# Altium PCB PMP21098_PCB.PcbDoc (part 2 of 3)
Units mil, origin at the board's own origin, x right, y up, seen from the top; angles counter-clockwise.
Board outline 5551.18 x 2125.98 mil, 4 copper layers (Top Layer, Signal Layer 1, Signal Layer 2, Bottom Layer), stack 61.6 mil thick; 197 components, 100 nets, 482 pads, 134 vias.
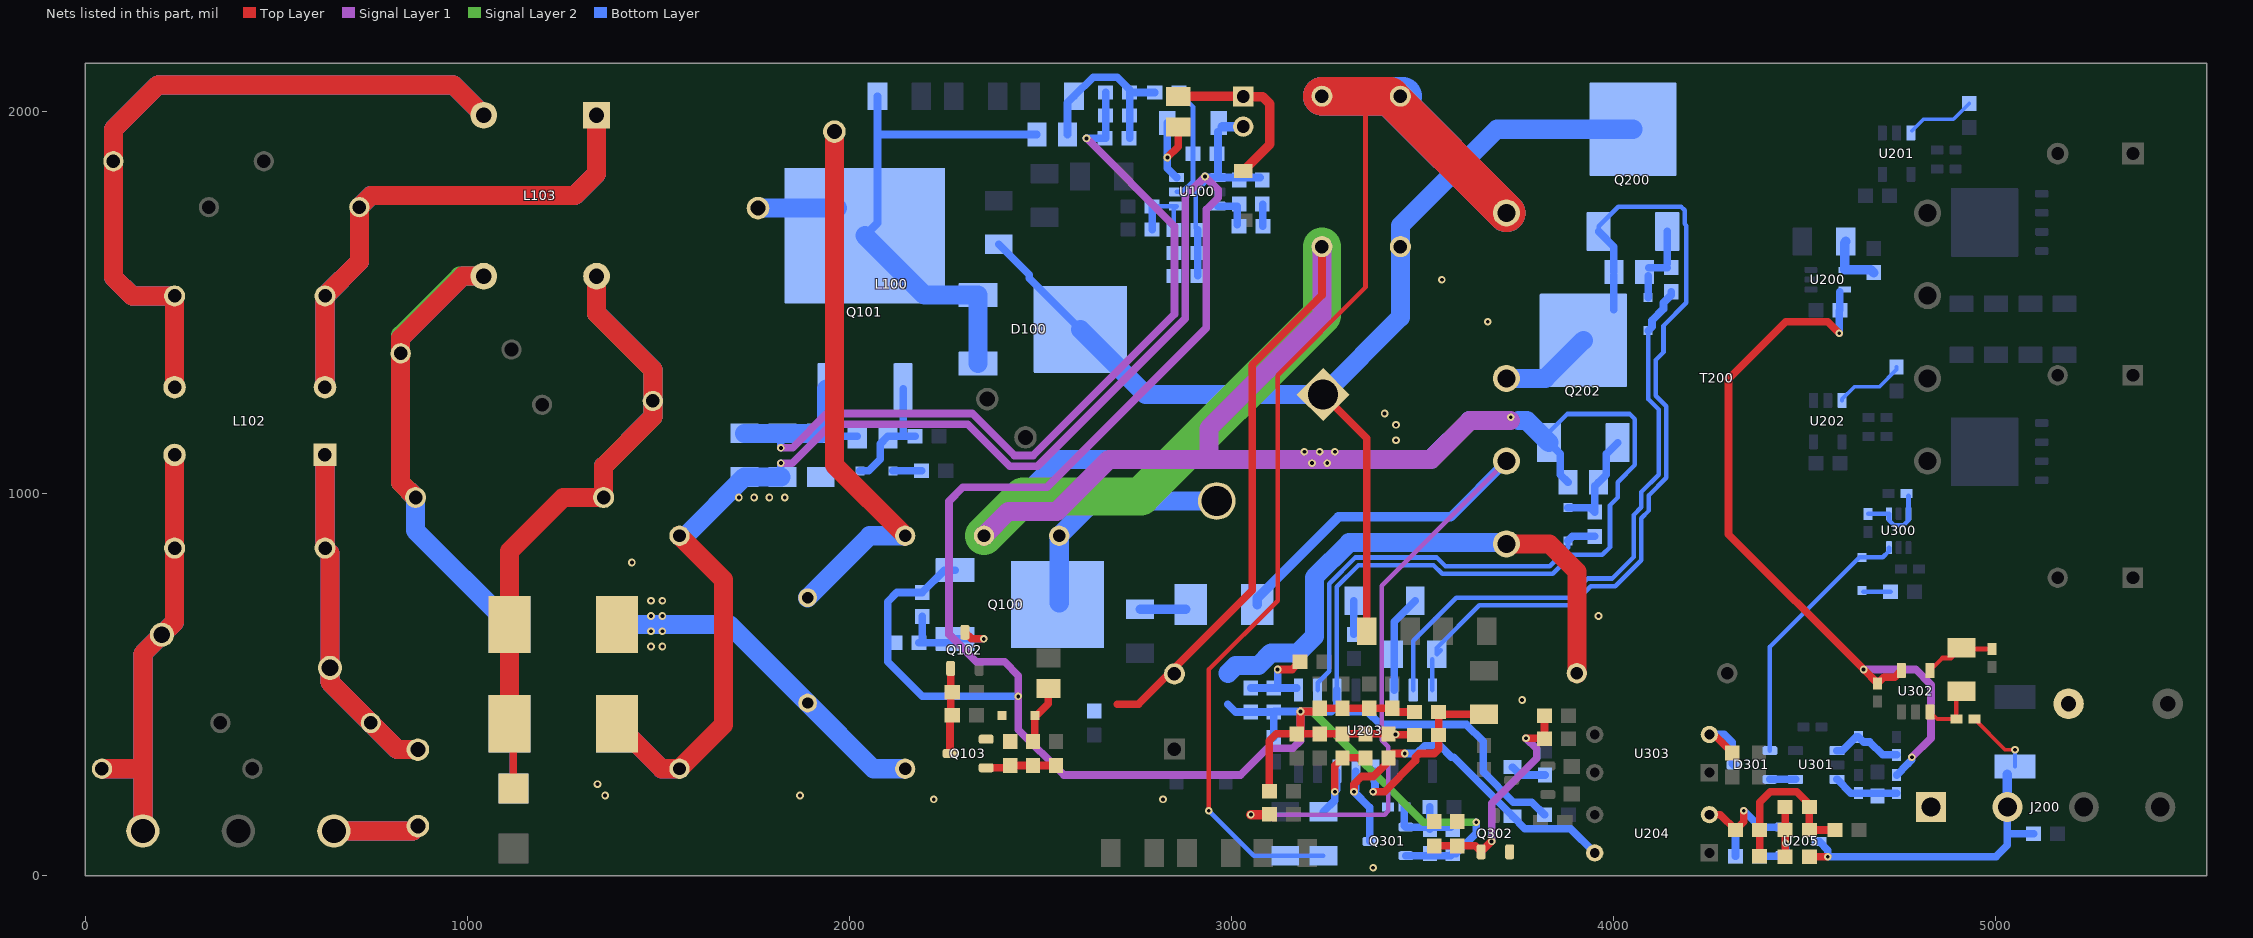
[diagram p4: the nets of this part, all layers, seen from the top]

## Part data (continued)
C122: "CAP, CERM, 10 pF, 10 V,+/- 10%, X7R, 0603", Cap_Case=0603, Manufacturer=AVX, Supplier Part Number 1=0603ZC100KAT2A-ND, TempCo=X7R, Tolerance_%=10, Value1=Unknown, Value2=10V, ValueDisplayed=10pF
C123: "CAP, CERM, 2200 pF, 50 V,+/- 10%, X7R, 0603", Cap_Case=0603, Manufacturer=Kemet, Supplier Part Number 1=399-1085-1-ND, TempCo=X7R, Tolerance_%=10, Value2=50V, ValueDisplayed=2200pF
C200 C213: "CAP, CERM, 1uF, 16V, +/-10%, X5R, 0603", Cap_Case=0603, Manufacturer=Kemet, Supplier Part Number 1=399-5090-1-ND, TempCo=X5R, Tolerance_%=10, Value1=Unknown, Value2=16V, ValueDisplayed=1µF
C201 C205: library part B32021A3332M289, "CAP FILM 10000PF 10% 630VDC RAD", Manufacturer="EPCOS (TDK)", Tolerance_%=20, Value1=Unknown, Value2=630V, ValueDisplayed=0.01µF
C202 C203 C211 C212: "CAP, CERM, 22 µF, 16 V,+/- 20%, X7R, 1206", Cap_Case=1206, Manufacturer="Taiyo Yuden", Supplier Part Number 1=587-4319-1-ND, TempCo=X7R, Tolerance_%=20, Value2=16V, ValueDisplayed=22µF
C204: "CAP, CERM, 1 µF, 25 V,+/- 10%, X5R, 1206", Cap_Case=1206, Manufacturer=MuRata, Supplier Part Number 1=490-1807-1-ND, TempCo=X5R, Tolerance_%=10, Value1="0.01 ohm", Value2=25V, ValueDisplayed=1µF
C206: "CAP, CERM, 150 pF, 630 V, +/- 5%, C0G/NP0, 1206", Cap_Case=1206, Manufacturer=MuRata, Supplier Part Number 1=490-5274-1-ND, TempCo=C0G/NP0, Tolerance_%=5, Value1=Unknown, Value2=630V, ValueDisplayed=150pF
C207: "CAP, CERM, 150 pF, 630 V,+/- 5%, C0G/NP0, 1206", Cap_Case=1206, Manufacturer=MuRata, Supplier Part Number 1=490-5274-1-ND, TempCo=C0G/NP0, Tolerance_%=5, Value2=630V, ValueDisplayed=150pF
C208: library part APS-160ELL331MJC5S, "CAP ALUM POLY 470UF 20% 16V T/H", Manufacturer=Chemi-Con, Tolerance_%=20, Value1="0.014 ohm", Value2=16V, ValueDisplayed=470µF
C209 C210: library part UHW1C222MHD, "CAP ALUM 2200UF 20% 16V RADIAL", Cap_Case=12.5x20mm, Manufacturer=Panasonic, Tolerance_%=20, Value2=16V, ValueDisplayed=2200µF
C215: library part CMP-0009602-2, "CAP, CERM, 2200 pF, 250 V, +/- 20%, E, Disc 10x8mm", Cap_Case=CAPRD1000W60D1000H1400, Manufacturer=MuRata, Supplier Part Number 1=490-7048-ND, TempCo=E, Tolerance_%=20%, Value1=Unknown, Value2=250V, ValueDisplayed=2200pF
C216 C218: "CAP, CERM, 2.2 µF, 16 V,+/- 20%, X5R, 0603", Cap_Case=0603, Manufacturer="Wurth Elektronik", Supplier Part Number 1=732-7915-1-ND, TempCo=X5R, Tolerance_%=20, Value2=16V, ValueDisplayed=2.2µF
C217 C219: "CAP, CERM, 0.1 µF, 25 V,+/- 5%, X7R, 0603", Cap_Case=0603, Manufacturer=AVX, Supplier Part Number 1=478-3713-1-ND, TempCo=X7R, Tolerance_%=5, Value1="0.05 ohm", Value2=25V, ValueDisplayed=0.1µF
C220: "CAP, CERM, 2.2 µF, 16 V, +/- 10%, X7R, 1206", Cap_Case=1206, Manufacturer=Kemet, Supplier Part Number 1=80-C1206C225K4R, TempCo=X7R, Tolerance_%=10, Value1="0.009 ohm", Value2=16V, ValueDisplayed=2.2µF
C221: "CAP, CERM, 100 pF, 50 V,+/- 5%, C0G/NP0, 0603", Cap_Case=0603, Manufacturer=AVX, Supplier Part Number 1=478-1175-1-ND, TempCo=C0G/NP0, Tolerance_%=5, Value1="0.119 ohm", Value2=50V, ValueDisplayed=100pF
C222: "CAP, CERM, 0.047 µF, 25 V,+/- 5%, X7R, 0603", Cap_Case=0603, Manufacturer=AVX, Supplier Part Number 1=478-3716-1-ND, TempCo=X7R, Tolerance_%=5, Value1="0.052 ohm", Value2=25V, ValueDisplayed=0.047µF
C223 C224: "CAP, CERM, 2.2 µF, 35 V, +/- 10%, X5R, 0603", Cap_Case=0603, Manufacturer=MuRata, Supplier Part Number 1=490-7204-6-ND, TempCo=X5R, Tolerance_%=10, Value1=Unknown, Value2=35V, ValueDisplayed=2.2µF
C225: "CAP, CERM, 47 pF, 50 V, +/- 1%, C0G/NP0, 0603", Cap_Case=0603, Manufacturer=MuRata, Supplier Part Number 1=490-9687-1-ND, TempCo=C0G/NP0, Tolerance_%=1, Value1=Unknown, Value2=50V, ValueDisplayed=47pF
C226: library part B41896C7687M000, "CAP ALUM 1000UF 20% 35V RADIAL", Cap_Case=12.5x25mm, Manufacturer=Panasonic, Tolerance_%=20, Value1="0.041 ohm", Value2=35V, ValueDisplayed=1000µF
C227: "CAP, CERM, 3300 pF, 50 V, +/- 5%, C0G/NP0, 0603", Cap_Case=0603, Manufacturer=MuRata, Supplier Part Number 1=GRM1885C1H332JA01D-ND, TempCo=C0G/NP0, Tolerance_%=5, Value1=Unknown, Value2=50V, ValueDisplayed=3300pF
C228 C229 C230: "CAP, CERM, 4.7 µF, 16 V, +/- 10%, X5R, 0603", Cap_Case=0603, Manufacturer=MuRata, Supplier Part Number 1=490-10481-1-ND, TempCo=X5R, Tolerance_%=10, Value1=Unknown, Value2=16V, ValueDisplayed=4.7µF
C231: "CAP, CERM, 0.01 µF, 100 V,+/- 5%, X7R, 0603", Cap_Case=0603, Manufacturer=AVX, Supplier Part Number 1=478-3700-1-ND, TempCo=X7R, Tolerance_%=5, Value1="0.098 ohm", Value2=100V, ValueDisplayed=0.01µF
C232: "CAP, CERM, 0.047 µF, 50 V,+/- 10%, X7R, 0603", Cap_Case=0603, Manufacturer=TDK, Supplier Part Number 1=445-1313-1-ND, TempCo=X7R, Tolerance_%=10, Value1="0.049007 ohm", Value2=50V, ValueDisplayed=0.047µF
C233: "CAP, CERM, 0.012 µF, 25 V,+/- 5%, C0G/NP0, 0603", Cap_Case=0603, Manufacturer=Kemet, Supplier Part Number 1=399-8997-1-ND, TempCo=C0G/NP0, Tolerance_%=5, Value2=25V, ValueDisplayed=0.012µF
C234: "CAP, CERM, 2.2 pF, 50 V, +/- 11%, C0G/NP0, 0603", Cap_Case=0603, Manufacturer=AVX, Supplier Part Number 1=478-1155-1-ND, TempCo=C0G/NP0, Tolerance_%=11, Value1="1.033 ohm", Value2=50V, ValueDisplayed=2.2pF
C235: "CAP, CERM, 220 pF, 50 V, +/- 10%, X7R, 0603", Cap_Case=0603, Manufacturer=MuRata, Supplier Part Number 1=490-1483-1-ND, TempCo=X7R, Tolerance_%=10, Value1=Unknown, Value2=50V, ValueDisplayed=220pF
C300 C301: "CAP, CERM, 0.1uF, 16V, +/-10%, X5R, 0402", Cap_Case=0402, Manufacturer=MuRata, Supplier Part Number 1=490-5415-1-ND, TempCo=X5R, Tolerance_%=10, Value1=Unknown, Value2=16V, ValueDisplayed=0.1µF
C302: "CAP, CERM, 47 pF, 500 V,+/- 5%, C0G/NP0, 1206", Cap_Case=1206, Manufacturer=AVX, Supplier Part Number 1=12067A470JAT2A-ND, TempCo=C0G/NP0, Tolerance_%=5, Value2=500V, ValueDisplayed=47pF
C303: "CAP, CERM, 10 pF, 50 V,+/- 4%, C0G/NP0, 0402", Cap_Case=0402, Manufacturer=MuRata, Supplier Part Number 1=490-11374-1-ND, TempCo=C0G/NP0, Tolerance_%=4, Value2=50V, ValueDisplayed=10pF
C304: "CAP, CERM, 100 pF, 50 V,+/- 5%, C0G/NP0, 0402", Cap_Case=0402, Manufacturer=MuRata, Supplier Part Number 1=81-GRM1555C1H101JA1D, TempCo=C0G/NP0, Tolerance_%=5, Value2=50V, ValueDisplayed=100pF
C305: "CAP, CERM, 0.1 µF, 25 V, +/- 10%, X5R, 0402", Cap_Case=0402, Manufacturer=MuRata, Supplier Part Number 1=81-GRM155R61E104KA7D, TempCo=X5R, Tolerance_%=10, Value1=Unknown, Value2=25V, ValueDisplayed=0.1µF
C306: "CAP, CERM, 0.01 µF, 25 V,+/- 5%, C0G/NP0, AEC-Q200 Grade 1, 0603", Cap_Case=0603, Manufacturer=Kemet, Supplier Part Number 1=399-14102-1-ND, TempCo=C0G/NP0, Tolerance_%=5, Value2=25V, ValueDisplayed=0.01µF
C307: "CAP, CERM, 0.022 µF, 50 V,+/- 10%, X7R, 0603", Cap_Case=0603, Manufacturer=Kemet, Supplier Part Number 1=399-1280-1-ND, TempCo=X7R, Tolerance_%=10, Value2=50V, ValueDisplayed=0.022µF
D100: library part STTH5R06B-TR, "DIODE GEN PURP 600V 5A DPAK", Manufacturer=STMicroelectronics, Value1=5A, Value2=2.9V
D101 D102 D103 D104: "Diode, P-N, 600 V, 5 A, SMC", Manufacturer=Vishay-Semiconductor, Supplier Part Number 1=S5J-E3/57TGITR-ND, Value1=5A, Value2=1.15V
D105 D108 D200 D201: "Diode, Switching, 100 V, 0.2 A, SOD-323", Manufacturer="Micro Commercial Components", Supplier Part Number 1=MMDL914-TPMSCT-ND, Value1=0.2A, Value2=1V
D106 D107: "Diode, Ultrafast, 600V, 1A, SMA", Manufacturer="ON Semiconductor", Supplier Part Number 1=MURA160T3GOSCT-ND, Value1=1A, Value2=600V
D109: "Diode, Switching, 100 V, 0.15 A, SOD-123FL", Manufacturer=Vishay-Semiconductor, Supplier Part Number 1=1N4148WFL-G3-08GICT-ND, Value1=0.15A, Value2=1.2V
D202: "Diode, Schottky, 60 V, 1 A, AEC-Q101, SMB", Manufacturer=STMicroelectronics, Supplier Part Number 1=497-13277-1-ND, Value1=1A, Value2=0.67V
D204: "Diode, Ultrafast, 600 V, 1 A, AEC-Q101, SMAF", Manufacturer="Fairchild Semiconductor", Supplier Part Number 1=ES1JAFCT-ND, Value1=1A, Value2=1.7V
D205: "Diode, Ultrafast, 100 V, 0.15 A, SOD-123", Manufacturer="Diodes Inc.", Supplier Part Number 1=1N4148W-FDICT-ND, Value1=0.15A, Value2=1.25V
D206: "Diode, Zener, 6.2 V, 500 mW, SOD-123", Manufacturer="Diodes Inc.", Power_W=0.5, Supplier Part Number 1=MMSZ5234B-FDICT-ND, Value1=0.5W
D300: library part BAT42WS-7-F, "Diode, Schottky, 30V, 0.2A, SOD-323", Manufacturer="Diodes Inc.", Supplier Part Number 1=BAT42WSDICT-ND, Value1=0.2A, Value2=30V
D301: "Diode, Schottky, 70 V, 0.07 A, SOT-23", Manufacturer="Diodes Inc.", Supplier Part Number 1=BAS7006ZXCT-ND, Value1=0.07A, Value2=1.7V
D302: library part MM5Z5V6ST1G, "DIODE ZENER 15V 200MW SOD523", Manufacturer="ON Semiconductor", Power_W=0.5, Value1=0.5W
F100: "Fuse, 3.15 A, 250VAC/VDC, TH", Irating_A=3.15A, Manufacturer=Littelfuse, Supplier Part Number 1=WK4224CT-ND
J200: "Terminal Block, 5.08 mm, 4x1, Brass, TH", Color=Blue, Current_A=15, Manufacturer="On-Shore Technology", Supplier Part Number 1=ED2227-ND, Voltage_V=300
L100: "Inductor, 200 µH, 0.235 ohm, TH", Manufacturer="Wurth Elektronik", Value1="0.235 ohm", Value2=A, ValueDisplayed=200µH
L101: library part 7447020, "100µH Unshielded Toroidal Inductor 2A 80 mOhm Max Radial", Manufacturer="Wurth Elektronik", Supplier Part Number 1=732-1424-ND, Value1="0.16 ohm", Value2=2A, ValueDisplayed=100µH
L102: "Coupled inductor, 1 mH, 2 A, 0.045 ohm, TH", Manufacturer="Wurth Elektronik", Supplier Part Number 1=732-1435-ND, ValueDisplayed=1mH
L103: "Coupled inductor, 10 mH, 2 A, 0.125 ohm, TH", Manufacturer="Wurth Elektronik", Supplier Part Number 1=732-1447-ND, ValueDisplayed=10mH
Q100: "MOSFET, N-CH, 600 V, 11 A, DPAK", Alternate Manufacturer=None, Manufacturer=STMicroelectronics, Supplier Part Number 1=497-13863-1-ND, Value1="? ohm", Value2="24.5 nC"
Q101: library part IPB60R199CPATMA1, "MOSFET, N-CH, 600 V, 16 A, DDPAK", Alternate Manufacturer=None, Manufacturer="Infineon Technologies", Supplier Part Number 1=IPB60R199CPCT-ND, Value1="? ohm", Value2="32 nC"
Q102: library part "MMBT4403, Fairchild Semiconductor", "Transistor, PNP, 40 V, 0.6 A, SOT-23", Manufacturer="Fairchild Semiconductor", Supplier Part Number 1=MMBT4403FSCT-ND, Value1="0.6 A", Value2=500
Q103 Q302: library part "MMBT4401-7-F, Diodes Inc.", "Transistor, NPN, 40 V, 0.15 A, SOT-23", Manufacturer="Diodes Inc.", Supplier Part Number 1=MMBT4401-FDICT-ND, Value1="0.15 A", Value2=300
Q200 Q202: "MOSFET, N-CH, 550 V, 13 A, DPAK", Alternate Manufacturer=None, Manufacturer=STMicroelectronics, Supplier Part Number 1=497-15111-1-ND, Value1="? ohm", Value2="19.5 nC"
Q201 Q203: "MOSFET, N-CH, 40 V, 15 A, DQJ0008A (VSONP-8)", Alternate Manufacturer=None, Manufacturer="Texas Instruments", Supplier Part Number 1=296-30572-1-ND, Value1="0.0098 ohm", Value2="7.7 nC"
Q300: library part "MMBT3906, Fairchild Semiconductor", "Transistor, PNP, 40 V, 0.2 A, SOT-23", Manufacturer="Fairchild Semiconductor", Supplier Part Number 1=MMBT3906FSCT-ND, Value1="0.2 A", Value2=300
Q301: "MOSFET, N-CH, 60V, 0.26A, SOT-23", Alternate Manufacturer=None, Manufacturer="ON Semiconductor", Supplier Part Number 1=2N7002ET1GOSCT-ND, Value1="3 ohm", Value2="0.81 nC"
R100 R101 R105 R106 R109 R115: "RES, 3.24 M, 1%, 0.25 W, 1206", Manufacturer=Vishay-Dale, Power_W=0.25, Supplier Part Number 1=541-3.24MFCT-ND, TempCo="100 ppm/C", Tolerance_%=1, Value1=1%, Value2=0.25W, Value_Code=3M24, ValueDisplayed=3.24M
R102 R201 R208: "RES, 10.0, 1%, 0.1 W, 0603", Manufacturer=Vishay-Dale, Power_W=0.1, Supplier Part Number 1=541-10.0HCT-ND, TempCo="100 ppm/C", Tolerance_%=1, Value1=1%, Value2=0.1W, Value_Code=10R0, ValueDisplayed=10.0
R103: "RES, 1.00 M, 1%, 0.1 W, 0603", Manufacturer=Vishay-Dale, Power_W=0.1, Supplier Part Number 1=541-1.00MHCT-ND, TempCo="100 ppm/C", Tolerance_%=1, Value1=1%, Value2=0.1W, Value_Code=1M00, ValueDisplayed=1.00M
R104: "RES, 20.0 k, 1%, 0.125 W, 0805", Manufacturer=Vishay-Dale, Power_W=0.125, Supplier Part Number 1=541-20.0KCCT-ND, TempCo="100 ppm/C", Tolerance_%=1, Value1=1%, Value2=0.125W, Value_Code=20k0, ValueDisplayed=20.0k
R107: "RES, 1.00, 1%, 0.1 W, 0603", Manufacturer=Vishay-Dale, Power_W=0.1, Supplier Part Number 1=52K8059, TempCo="100 ppm/C", Tolerance_%=1, Value1=1%, Value2=0.1W, Value_Code=1R00, ValueDisplayed=1.00
R108: "RES, 24.3 k, 1%, 0.1 W, 0603", Manufacturer=Vishay-Dale, Power_W=0.1, Supplier Part Number 1=541-24.3KHCT-ND, TempCo="100 ppm/C", Tolerance_%=1, Value1=1%, Value2=0.1W, Value_Code=24k3, ValueDisplayed=24.3k
R110: "RES, 3.0 k, 5%, 0.1 W, 0603", Manufacturer=Vishay-Dale, Power_W=0.1, Supplier Part Number 1=541-3.0KGCT-ND, TempCo="200 ppm/C", Tolerance_%=5, Value1=5%, Value2=0.1W, Value_Code=3k00, ValueDisplayed=3.0k
R111 R303 R305: "RES, 10.0 k, 1%, 0.1 W, 0603", Manufacturer=Vishay-Dale, Power_W=0.1, Supplier Part Number 1=541-10.0KHCT-ND, TempCo="100 ppm/C", Tolerance_%=1, Value1=1%, Value2=0.1W, Value_Code=10k0, ValueDisplayed=10.0k
R112 R113: "RES, 0.13, 1%, 0.5 W, 1206", Manufacturer="Stackpole Electronics Inc", Power_W=0.5, Supplier Part Number 1=CSR1206FTR130CT-ND, TempCo="100 ppm/C", Tolerance_%=1, Value1=1%, Value2=0.5W, Value_Code=R130, ValueDisplayed=0.13
R114: "RES, 453 k, 1%, 0.25 W, 1206", Manufacturer=Vishay-Dale, Power_W=0.25, Supplier Part Number 1=541-453KFCT-ND, TempCo="100 ppm/C", Tolerance_%=1, Value1=1%, Value2=0.25W, Value_Code=453k
R116 R123: "RES, 75.0 k, 1%, 0.1 W, 0603", Manufacturer=Vishay-Dale, Power_W=0.1, Supplier Part Number 1=541-75.0KHCT-ND, TempCo="100 ppm/C", Tolerance_%=1, Value1=1%, Value2=0.1W, Value_Code=75k0, ValueDisplayed=75.0k
R117 R210: "RES, 36.5 k, 1%, 0.1 W, 0603", Manufacturer=Vishay-Dale, Power_W=0.1, Supplier Part Number 1=541-36.5KHCT-ND, TempCo="100 ppm/C", Tolerance_%=1, Value1=1%, Value2=0.1W, Value_Code=36k5, ValueDisplayed=36.5k
R118: "RES, 120 k, 1%, 0.1 W, 0603", Manufacturer="Yageo America", Power_W=0.1, Supplier Part Number 1=311-120KHRCT-ND, TempCo="200 ppm/C", Tolerance_%=1, Value1=1%, Value2=0.1W, Value_Code=120k
R119: "RES, 49.9 k, 1%, 0.1 W, 0603", Manufacturer=Vishay-Dale, Power_W=0.1, Supplier Part Number 1=541-49.9KHCT-ND, TempCo="100 ppm/C", Tolerance_%=1, Value1=1%, Value2=0.1W, Value_Code=49k9, ValueDisplayed=49.9k
R120 R124: "RES, 390 k, 1%, 0.1 W, 0603", Manufacturer="Yageo America", Power_W=0.1, Supplier Part Number 1=311-390KHRCT-ND, TempCo="200 ppm/C", Tolerance_%=1, Value1=1%, Value2=0.1W, Value_Code=390k
R121: "RES, 10.0, 1%, 0.125 W, 0805", Manufacturer=Vishay-Dale, Power_W=0.125, Supplier Part Number 1=541-10.0CCT-ND, TempCo="100 ppm/C", Tolerance_%=1, Value1=1%, Value2=0.125W, Value_Code=10R0, ValueDisplayed=10.0
R122: "RES, 180 k, 1%, 0.1 W, 0603", Manufacturer="Yageo America", Power_W=0.1, Supplier Part Number 1=311-180KHRCT-ND, TempCo="200 ppm/C", Tolerance_%=1, Value1=1%, Value2=0.1W, Value_Code=180k
R200 R205: "RES, 10.0 k, 1%, 0.125 W, 0805", Manufacturer=Vishay-Dale, Power_W=0.125, Supplier Part Number 1=541-10.0KCCT-ND, TempCo="100 ppm/C", Tolerance_%=1, Value1=1%, Value2=0.125W, Value_Code=10k0, ValueDisplayed=10.0k
R202 R226 R304: "RES, 0, 5%, 0.1 W, 0603", Manufacturer=Vishay-Dale, Power_W=0.1, Supplier Part Number 1=541-0.0GCT-ND, TempCo="200 ppm/C", Tolerance_%=5, Value1=5%, Value2=0.1W, Value_Code=0000, ValueDisplayed=0
R203 R204 R206 R207: "RES, 0, 5%, 0.063 W, 0402", Manufacturer=Vishay-Dale, Power_W=0.063, Supplier Part Number 1=541-0.0JCT-ND, TempCo="200 ppm/C", Tolerance_%=5, Value1=5%, Value2=0.063W, Value_Code=0000, ValueDisplayed=0
R209: "RES, 0.001, 1%, 1.5 W, 2010", Manufacturer="Stackpole Electronics Inc", Power_W=1.5, Supplier Part Number 1=CSNL2010FT1L00CT-ND, TempCo="50 ppm/C", Tolerance_%=1, Value1=1%, Value2=1.5W, Value_Code=1L000, ValueDisplayed=0.001
R211: "RES, 8.45 k, 1%, 0.1 W, 0603", Manufacturer="Yageo America", Power_W=0.1, Supplier Part Number 1=311-8.45KHRCT-ND, TempCo="200 ppm/C", Tolerance_%=1, Value1=1%, Value2=0.1W, Value_Code=8k45, ValueDisplayed=8.45k
R212: "RES, 2.2, 5%, 0.1 W, 0603", Manufacturer=Vishay-Dale, Power_W=0.1, Supplier Part Number 1=541-2.2GCT-ND, TempCo="200 ppm/C", Tolerance_%=5, Value1=5%, Value2=0.1W, Value_Code=2R20, ValueDisplayed=2.2
R213: "RES, 20.0, 1%, 0.1 W, 0603", Manufacturer=Vishay-Dale, Power_W=0.1, Supplier Part Number 1=541-20.0HCT-ND, TempCo="100 ppm/C", Tolerance_%=1, Value1=1%, Value2=0.1W, Value_Code=20R0, ValueDisplayed=20.0
R214 R220 R223: "RES, 4.99 M, 1%, 0.25 W, 1206", Manufacturer=Vishay-Dale, Power_W=0.25, Supplier Part Number 1=541-4.99MFCT-ND, TempCo="100 ppm/C", Tolerance_%=1, Value1=1%, Value2=0.25W, Value_Code=4M99, ValueDisplayed=4.99M
R215: "RES, 10.0 k, 1%, 0.1 W, 0603", Manufacturer=Panasonic, Power_W=0.1, Supplier Part Number 1=P10.0KHCT-ND, TempCo="100 ppm/C", Tolerance_%=1, Value1=1%, Value2=0.1W, Value_Code=10k0, ValueDisplayed=10.0k
R216: "RES, 1.50 k, 1%, 0.1 W, 0603", Manufacturer=Vishay-Dale, Power_W=0.1, Supplier Part Number 1=541-1.50KHCT-ND, TempCo="100 ppm/C", Tolerance_%=1, Value1=1%, Value2=0.1W, Value_Code=1k50, ValueDisplayed=1.50k
R217 R218 R219: "RES, 1.65 k, 1%, 0.25 W, 1206", Manufacturer=Vishay-Dale, Power_W=0.25, Supplier Part Number 1=541-1.65KFCT-ND, TempCo="100 ppm/C", Tolerance_%=1, Value1=1%, Value2=0.25W, Value_Code=1k65, ValueDisplayed=1.65k
R221: "RES, 6.04 k, 1%, 0.1 W, 0603", Manufacturer=Vishay-Dale, Power_W=0.1, Supplier Part Number 1=541-6.04KHCT-ND, TempCo="100 ppm/C", Tolerance_%=1, Value1=1%, Value2=0.1W, Value_Code=6k04, ValueDisplayed=6.04k
R222 R227: "RES, 150 k, 1%, 0.1 W, 0603", Manufacturer=Vishay-Dale, Power_W=0.1, Supplier Part Number 1=541-150KHCT-ND, TempCo="100 ppm/C", Tolerance_%=1, Value1=1%, Value2=0.1W, Value_Code=150k
R224: "RES, 25.5 k, 1%, 0.1 W, 0603", Manufacturer=Vishay-Dale, Power_W=0.1, Supplier Part Number 1=541-25.5KHCT-ND, TempCo="100 ppm/C", Tolerance_%=1, Value1=1%, Value2=0.1W, Value_Code=25k5, ValueDisplayed=25.5k
R225: "RES, 806 k, 1%, 0.1 W, 0603", Manufacturer=Vishay-Dale, Power_W=0.1, Supplier Part Number 1=541-806KHCT-ND, TempCo="100 ppm/C", Tolerance_%=1, Value1=1%, Value2=0.1W, Value_Code=806k
R228: "RES, 68.1, 1%, 0.1 W, 0603", Manufacturer=Vishay-Dale, Power_W=0.1, Supplier Part Number 1=541-68.1HCT-ND, TempCo="100 ppm/C", Tolerance_%=1, Value1=1%, Value2=0.1W, Value_Code=68R1, ValueDisplayed=68.1
R229: "RES, 44.2 k, 1%, 0.1 W, 0603", Manufacturer=Vishay-Dale, Power_W=0.1, Supplier Part Number 1=541-44.2KHCT-ND, TempCo="100 ppm/C", Tolerance_%=1, Value1=1%, Value2=0.1W, Value_Code=44k2, ValueDisplayed=44.2k
R230: "RES, 17.4 k, 1%, 0.1 W, 0603", Manufacturer=Vishay-Dale, Power_W=0.1, Supplier Part Number 1=541-17.4KHCT-ND, TempCo="100 ppm/C", Tolerance_%=1, Value1=1%, Value2=0.1W, Value_Code=17k4, ValueDisplayed=17.4k
R231: "RES, 49.9, 1%, 0.25 W, 1206", Manufacturer=Vishay-Dale, Power_W=0.25, Supplier Part Number 1=541-49.9FCT-ND, TempCo="100 ppm/C", Tolerance_%=1, Value1=1%, Value2=0.25W, Value_Code=49R9, ValueDisplayed=49.9
R300: "RES, 2.21 M, 1%, 0.1 W, 0603", Manufacturer=Vishay-Dale, Power_W=0.1, Supplier Part Number 1=541-2.21MHCT-ND, TempCo="100 ppm/C", Tolerance_%=1, Value1=1%, Value2=0.1W, Value_Code=2M21, ValueDisplayed=2.21M
R301: "RES, 619k ohm, 1%, 0.063W, 0402", Manufacturer=Vishay-Dale, Power_W=0.063, Supplier Part Number 1=541-619KLCT-ND, TempCo="100 ppm/C", Tolerance_%=1, Value1=1%, Value2=0.063W, Value_Code=619k
R302: "RES, 0 ohm, 5%, 0.063W, 0402", Manufacturer=Panasonic, Power_W=0.063, Supplier Part Number 1=P0.0JCT-ND, TempCo="600 ppm/C", Tolerance_%=5, Value1=5%, Value2=0.063W, Value_Code=0000
R306: "RES, 100 k, 1%, 0.063 W, 0402", Manufacturer=Vishay-Dale, Power_W=0.063, Supplier Part Number 1=541-100KLCT-ND, TempCo="100 ppm/C", Tolerance_%=1, Value1=1%, Value2=0.063W, Value_Code=100k
R307 R308: "RES, 4.75, 1%, 0.063 W, 0402", Manufacturer=Vishay-Dale, Power_W=0.063, Supplier Part Number 1=541-4.75LLCT-ND, TempCo="100 ppm/C", Tolerance_%=1, Value1=1%, Value2=0.063W, Value_Code=4R75, ValueDisplayed=4.75
R309: "RES, 2.00 k, 0.1%, 0.063 W, 0603", Manufacturer="TE Connectivity", Power_W=0.063, Supplier Part Number 1=6-1676481-1, TempCo="25 ppm/C", Tolerance_%=0.1, Value1=0.1%, Value2=0.063W, Value_Code=2k00, ValueDisplayed=2.00k
R310: "RES, 100, 1%, 0.125 W, AEC-Q200 Grade 1, 0402", Manufacturer="AT Ceramics", Power_W=0.125, TempCo=ppm/C, Tolerance_%=1, Value1=1%, Value2=0.125W, Value_Code=100R, ValueDisplayed=100
R311: "RES, 7.50 k, 1%, 0.1 W, 0603", Manufacturer="Yageo America", Power_W=0.1, Supplier Part Number 1=311-7.50KHRCT-ND, TempCo="200 ppm/C", Tolerance_%=1, Value1=1%, Value2=0.1W, Value_Code=7k50, ValueDisplayed=7.50k
R312: "RES, 432 k, 1%, 0.1 W, 0603", Manufacturer=Vishay-Dale, Power_W=0.1, Supplier Part Number 1=541-432KHCT-ND, TempCo="100 ppm/C", Tolerance_%=1, Value1=1%, Value2=0.1W, Value_Code=432k
R313: "RES, 2.0 k, 5%, 0.1 W, 0603", Manufacturer="Yageo America", Power_W=0.1, Supplier Part Number 1=311-2.0KGRCT-ND, TempCo="100 ppm/C", Tolerance_%=5, Value1=5%, Value2=0.1W, Value_Code=2k00, ValueDisplayed=2.0k
R314: "RES, 2.2 M, 5%, 0.1 W, 0603", Manufacturer=Vishay-Dale, Power_W=0.1, Supplier Part Number 1=541-2.2MGCT-ND, TempCo="200 ppm/C", Tolerance_%=5, Value1=5%, Value2=0.1W, Value_Code=2M20, ValueDisplayed=2.2M
R315: "RES, 30.1 k, 1%, 0.1 W, 0603", Manufacturer=Vishay-Dale, Power_W=0.1, Supplier Part Number 1=541-30.1KHCT-ND, TempCo="100 ppm/C", Tolerance_%=1, Value1=1%, Value2=0.1W, Value_Code=30k1, ValueDisplayed=30.1k
R316 R317: "RES, 41.2 k, 1%, 0.1 W, 0603", Manufacturer=Vishay-Dale, Power_W=0.1, Supplier Part Number 1=541-41.2KHCT-ND, TempCo="100 ppm/C", Tolerance_%=1, Value1=1%, Value2=0.1W, Value_Code=41k2, ValueDisplayed=41.2k
RT100: "Thermistor NTC, 10 ohm, 20%, Disc_11.5mmx6mm", Manufacturer=TDK, Power_W=2.1, Supplier Part Number 1=495-2094-ND, Tolerance_%=20
RV100: "Varistor 275V RMS 10MM Radial, TH", Manufacturer="EPCOS Inc", Supplier Part Number 1=495-1433-ND
T200: library part CMP-0077669-1, "Transformer, 600 uH, TH", Manufacturer="Wurth Elektronik", Supplier Part Number 1=732-5062-ND, ValueDisplayed=600µH
TP200: "Test Point, Miniature, Red, TH", Color=Red, Manufacturer=Keystone, Supplier Part Number 1=36-5000-ND
TP201: "Test Point, Miniature, Black, TH", Color=Black, Manufacturer=Keystone, Supplier Part Number 1=36-5001-ND
TP_L: "Test Point, Multipurpose, Red, TH", Color=Red, Manufacturer=Keystone, Supplier Part Number 1=36-5010-ND
TP_N: "Test Point, Multipurpose, Black, TH", Color=Black, Manufacturer=Keystone, Supplier Part Number 1=36-5011-ND
TP_PE: "Test Point, Multipurpose, White, TH", Color=White, Manufacturer=Keystone, Supplier Part Number 1=36-5012-ND
U100: "6-Pin Single-Phase Transition-Mode PFC Controller, DBV0006A (SOT-23-6)", Alternate Manufacturer="Texas Instruments"
U200: library part TPS71533DCKR, "50 mA, 24 V, 3.2-uA Iq, Low-Dropout Linear Regulator in SC70 Package, DCK0005A (SOT-SC70-5)", Alternate Manufacturer="Texas Instruments"
U201 U202: library part UCC24612-1DBVR, "UCC24612-2DBV, DBV0005A (SOT-23-5)", Alternate Manufacturer="Texas Instruments", Alternate PartNumber=UCC24612-2DBVT
U203: library part UCC25630DDB, "Enhanced LLC Resonant Controller with Driver, DDB0014A", Alternate Manufacturer="Texas Instruments"
U204: library part VO618A, "OPTOISOLATOR 5.3KV TRANS 4-DIP", Manufacturer=Vishay-Semiconductor, Voltage_Isolation_Vrms=5300V
U205: "Low-Voltage Adjustable Precision Shunt Regulator, 80 mA, -40 to 125 degC, 3-pin SOT-23 (DBZ), Green (RoHS & no Sb/Br)", Alternate Manufacturer="Texas Instruments", Alternate PartNumber=Equivalent, Rating=Catalog, Supplier Part Number 1=296-17972-2-ND, Temp Coeff(Max)(ppm/ degree C)=129
U300: "Resistor-Programmable, up to 18V-Capable Temp Switch and Analog Out Sensor, DCK0006A (SOT-SC70-6)", Alternate Manufacturer="Texas Instruments", Alternate PartNumber=TMP300BIDCKT
U301: "SINGLE DIFFERENTIAL COMPARATOR, DBV0005A (SOT-23-5)", Alternate Manufacturer="Texas Instruments", Alternate PartNumber=TL331IDBVT
U302: "Low- and High-Side Measurement, Multichannel, Voltage Output, Current-Sense Amplifier, DBV0005A (SOT-23-5)", Alternate Manufacturer="Texas Instruments"
U303: library part FOD817A, "OPTOISOLATOR 5KV TRANSISTOR 4DIP", Manufacturer="Fairchild Semiconductor", Supplier Part Number 1=FOD817D-ND, Voltage_Isolation_Vrms=5000V

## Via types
v1: diameter 20, hole 10, Top Layer to Bottom Layer, 134 vias

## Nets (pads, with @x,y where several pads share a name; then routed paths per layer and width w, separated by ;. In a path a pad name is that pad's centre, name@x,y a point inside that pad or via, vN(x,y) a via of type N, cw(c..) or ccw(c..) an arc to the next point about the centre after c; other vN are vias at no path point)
5V: C200.1 C305.1 R306.2 U200.5 U302.5 | length 1972.7
  Top Layer w20: v1(4590,1420) 4560,1450 4450,1450 4300,1300 4300,893.62 v1(4653.62,540) C305.1@4690,503.62 4706.38,520 4735.31,520 U302.5@4752.6,537.28
  Signal Layer 1 w20: v1(4653.62,540) 4790,540 4830,500 4830,360 v1(4780,310)
  Bottom Layer w20: v1(4590,1420) C200.1@4590,1478.5 ; C200.1@4591.5,1480 U200.5@4591.5,1528.5 ; R306.2@4740,263.62 4740.08,263.62 4769.69,293.23 4769.69,293.31 4780,303.62 v1(4780,310)
BLK: C235.1 R223.1 R229.2 U203.4 | length 488.8
  Top Layer w20: v1(3370,220) 3400,220 3480.75,300.75 3480.75,310 3490.75,320 3530,320 3541.5,331.5 R229.2@3541.5,428.7 ; R229.2@3547.28,422.91 R223.1@3660,422.91
  Bottom Layer w20: v1(3370,220) 3375,225 U203.4@3375,273.7
FB: C225.1 D206.2 Q301.3 U203.5 U204.4 | length 1015.9
  Top Layer w20: v1(3320,220) 3320,240 3340,260 3371.02,260 3410,298.98 C225.1@3410,308.5 3421.5,320 v1(3452.87,320)
  Bottom Layer w20: U203.5@3325,273.7 3325,225 v1(3320,220) 3361.46,178.54 Q301.3@3361.46,90 ; v1(3452.87,320) 3484.88,320 3504.88,340 3545.12,340 3575.12,310 3580.45,310 D206.2@3734.92,155.53 3767.03,123.43 3886.57,123.43 U204.4@3950,60
GND: C107.1 C108.1 C113.2 C119.2 C120.2 C121.2 C122.2 C123.2 C205.2 C215.2 C223.1 C224.1 C225.2 C226.2 C227.1 C228.2 C229.2 C230.2 C231.2 C232.2 C233.2 C234.2 C235.2 C306.2 C307.2 D103.2 D104.2 D108.2 D302.2 Q100.3 Q103.2 Q202.3 Q301.2 Q302.2 R103.1 R112.1 R113.1 R114.1 R119.1 R122.1 R123.1 R124.1 R205.1 R211.1 R226.1 R227.1 R228.1 R229.1 R314.1 R317.1 RT100.1 T200.6 U100.4 U203.11 | length 19974.7
  Top Layer w20: 2700,449.21 2755.87,449.21 3054,747.34 3054,1337.34 3236.03,1519.37 C205.2@3236.03,1646.57 ; R211.1@3098.5,221.3 3098.5,352.95 3117.05,371.5 C234.2@3170,371.5 ; C228.2@3221.5,430 v1(3180,430) 3180,381.5 C234.2@3170,371.5 ; C228.2@3230,438.5 C229.2@3290,438.5 C230.2@3360,438.5 C231.2@3420,438.5 ; C225.2@3410,371.5 R228.1@3350,371.5 C227.1@3290,371.5 C234.2@3170,371.5 ; C225.2@3412.8,368.7 C235.2@3478.5,368.7 ; C231.2@3429.8,428.7 R229.1@3478.5,428.7
  Top Layer w50: D103.2@1390.62,397.51 1508.13,280 C107.1@1554.72,280 1670,395.28 1670,774.72 C108.1@1554.72,890 ; T200.6@3718.82,868.66 3831.34,868.66 3903.15,796.85 C215.2@3903.15,530
  Signal Layer 1 w20: v1(1820,1080) 1850,1080 1952.13,1182.13 2309.17,1182.13 2419.06,1072.23 2491.65,1072.23 2877.87,1458.45 2877.87,1777.87 v1(2930,1830) 2965,1795 2965,1775 2933.62,1743.62 2933.62,1433.62 2516.49,1016.49 2296.49,1016.49 2260,980 2260,631.65 2331.65,560 2405.42,560 2441.47,523.95 v1(2441.47,469.43) 2441.47,382.29 2559.89,263.87 3023.03,263.87 3092.9,333.75 3160,333.75 3180,353.75 v1(3180,430)
  Signal Layer 1 w50: RT100.1@2351.57,890 2415.31,953.74 2542.48,953.74 2678.74,1090 2940,1090 ; C205.2@3236.03,1646.57 3236.03,1467.05 2940,1171.02 2940,1090 ; v1@3730,1191.3 3622.64,1191.3 3521.34,1090 2940,1090
  Signal Layer 2 w20: v1(3180,430) 3211.3,430 3501.3,140 v1(3640,140)
  Signal Layer 2 w100: RT100.1@2351.57,890 2454.19,992.61 2761.59,992.61 3236.03,1467.05 C205.2@3236.03,1646.57
  Bottom Layer w12: C123.2@2906.13,1695.37 2906.13,1789.89 2930,1813.76 v1(2930,1830) ; U203.11@3275,486.3 3275,756.55 3331.65,813.2 3527.92,813.2 3551.13,790 3840,790 3890,840 3970,840 3990,860 3990,970 4010,990 4010,1030 4055.26,1075.26 4055.26,1194.74 4041.55,1208.45 3878.45,1208.45 3830.36,1160.36 Q202.3@3830.36,1133.65
  Bottom Layer w20: R113.1@1820,1048.08 v1(1820,1080) ; Q100.3@2276.14,799.76 2248.27,799.76 R103.1@2190,741.5 2123.86,741.5 2100,717.64 2100,560 2190.57,469.43 v1(2441.47,469.43) ; R123.1@2911.5,1570 R124.1@2911.5,1630 C123.2@2911.5,1690 ; v1(2930,1830) 2932.6,1827.4 U100.4@2964.13,1827.4 ; C121.2@2964.13,1947.2 U100.4@2964.13,1827.4 ; 2990,449.21 3010.71,428.5 C232.2@3110,428.5 ; R122.1@3074.09,1827.4 U100.4@2964.13,1827.4 ; C224.1@3110,361.5 C232.2@3110,428.5 ; U203.11@3275,486.3 3275,445 ; Q301.2@3455.94,52.6 C306.2@3572.8,52.6 ; C306.2@3578.7,58.5 3587.05,58.5 3640,111.46 v1(3640,140) ; R226.1@3818.5,160 3785.61,192.9 3736.97,192.9 3657.87,272 3657.87,352.13 3614.21,395.79 3389.51,395.79 3355.3,430 3290,430 3275,445 ; Q202.3@3830.36,1133.65 3860,1104.02 3860,1050 R205.1@3880,1030 ; C232.2@3110,428.5 3111.5,430 v1(3180,430) 3260,430 3275,445
  Bottom Layer w25: C121.2@2974.8,1960.63 C119.2@3030,1960.63
  Bottom Layer w50: D104.2@1390.62,397.51 1508.13,280 C107.1@1554.72,280 ; C108.1@1570.83,890 R112.1@1724.45,1043.63 R113.1@1820,1043.63 ; RT100.1@2351.57,890 2551.57,1090 3521.34,1090 3622.64,1191.3 3710,1191.3 ; 2990,530 3010,550 3069.37,550 3102.24,582.87 3172.87,582.87 3216.25,626.25 3216.25,780.88 3307.32,871.95 3718.82,871.95 T200.6@3718.82,868.66 ; 3750,1191.3 3772.72,1191.3 Q202.3@3830.36,1133.65
  other v1: 3370,21.1 2220,200 2820,200 1360,210 1870,210 1340,240 3428.7,370 3760,460 3960,680 1430,820 1710,990 1750,990 1790,990 1830,990 3210,1080 3250,1080 3190,1110 3230,1110 3270,1110 3430,1140 3430,1180 3730,1200 3400,1210 3670,1450 3550,1560
HO: D200.1 R201.1 U203.15 | length 1553.9
  Bottom Layer w12: U203.15@3475,486.3 3475,615 3588,728 3881.65,728 3931.65,778 3995.68,778 4052,834.32 4052,944.32 4072,964.32 4072,1004.32 4117.26,1049.58 4117.26,1220.42 4090,1247.68 D200.1@4090,1426.69
  Bottom Layer w20: D200.1@4090,1426.69 4100,1436.69 4100,1453.44 4130,1483.44 4130,1500.01 4150,1520.01 R201.1@4150,1528.5
HS: C220.2 Q200.3 Q202.4 R200.1 T200.4 U203.16 | length 2458.7
  Bottom Layer w12: U203.16@3525,486.3 C220.2@3525,566.89 ; C220.2@3547.09,590 C220.2@3537.09,580 3537.09,597.09 3648.13,708.13 3890,708.13 3940,758.13 4003.91,758.13 4071.87,826.09 4071.87,936.09 4091.87,956.09 4091.87,996.09 4137.14,1041.35 4137.14,1228.65 4109.87,1255.91 4109.87,1350 4130,1370.13 4130,1440 4190,1500 4190,1701.2 4185.13,1706.06 4185.13,1741.96 4175.9,1751.2 4011.2,1751.2 3960.24,1700.24 Q200.3@3960.24,1686.14 ; R200.1@4000,1571.46 R200.1@4000,1580
  Bottom Layer w20: Q200.3@3960.24,1686.14 4000,1646.38 R200.1@4000,1580 ; Q202.4@4000,1481.24 R200.1@4000,1571.46
  Bottom Layer w50: T200.4@3718.82,1301.73 3820.49,1301.73 Q202.4@3920.13,1401.37
HV: C103.1 C201.1 D100.4 Q200.4 R106.2 R214.2 | length 2953
  Top Layer w20: C103.1@3239.19,1259.19 3352.91,1145.48 R214.2@3352.91,640
  Top Layer w50: C103.1@3239.19,1259.19 C103.1@3269.19,1259.19
  Bottom Layer w20: R106.2@2390,1652.91 2470,1572.91 2470,1563.86 D100.4@2603.86,1430
  Bottom Layer w50: D100.4@2603.86,1430 2774.66,1259.19 C103.1@3239.19,1259.19 3441.39,1461.39 C201.1@3441.39,1646.57 3441.39,1701.39 3693.86,1953.86 Q200.4@4050,1953.86
IN+: C213.1 J200.1 J200.2 R209.2 R230.1 R308.2 TP201.1 U205.3 | length 1016.9
  Top Layer w10: R308.2@4943.62,410 5023.62,330 v1(5050,330)
  Top Layer w20: R230.1@4511.5,50 v1(4560,50)
  Bottom Layer w10: R209.2@5050,286.3 v1(5050,330)
  Bottom Layer w20: U205.3@4537.24,90 4560,67.24 v1(4560,50) 5000,50 5030,80 5030,110 ; J200.2@5030,178.5 5030,110 ; C213.1@5098.5,110 5030,110
  Bottom Layer w25: J200.2@5030,180 R209.2@5030,266.3
ISNS: C206.1 C227.2 R228.2 U203.6 | length 277.9
  Top Layer w20: v1(3270,220) 3270,288.5 C227.2@3290,308.5 R228.2@3350,308.5
  Bottom Layer w20: C206.1@3240,167.09 3270,197.09 v1(3270,220) 3275,225 U203.6@3275,273.7
LO: D201.1 R208.1 U203.10 | length 1067.2
  Bottom Layer w12: U203.10@3225,486.3 3225,505 3255.13,535.13 3255.13,764.78 3323.42,833.08 3536.15,833.08 3559.36,809.87 3831.77,809.87 3880,858.11 D201.1@3880,876.69
  Bottom Layer w20: D201.1@3880,876.69 3891.81,888.5 R208.1@3950,888.5
NetC100_1: C100.1 C104.1 L102.4 RV100.2 TP_N.1 | length 4267.2
  Top Layer w50: C100.1@43.15,280 140.13,280 ; TP_N.1@150.13,117.51 150.13,580.95 RV100.2@200,630.82 233.28,664.1 C104.1@233.28,857.51 ; C104.1@233.15,857.64 L102.4@233.15,1101.42
  Signal Layer 1 w50: TP_N.1@150.13,117.51 150.13,580.95 RV100.2@200,630.82 233.28,664.1 C104.1@233.28,857.51 233.28,1101.29 L102.4@233.15,1101.42
  Signal Layer 2 w50: TP_N.1@150.13,117.51 150.13,580.95 RV100.2@200,630.82 233.28,664.1 C104.1@233.28,857.51 L102.4@233.28,1101.29
  Bottom Layer w50: C100.1@43.15,280 140.13,280 ; TP_N.1@150.13,117.51 150.13,580.95 RV100.2@200,630.82 233.28,664.1 C104.1@233.28,857.51 233.28,1101.29 L102.4@233.15,1101.42
NetC101_1: C101.1 C105.1 L102.3 L103.2 | length 7424.4
  Top Layer w50: L102.3@233.28,1278.71 C105.1@233.28,1517.51 122.49,1517.51 73.15,1566.85 C101.1@73.15,1870 73.15,1953.15 190,2070 962.99,2070 L103.2@1042.36,1990.63
  Signal Layer 1 w50: L102.3@233.15,1278.58 233.15,1517.38 122.62,1517.38 73.15,1566.85 C101.1@73.15,1870 73.15,1953.15 190,2070 962.99,2070 L103.2@1042.36,1990.63
  Signal Layer 2 w50: L102.3@233.15,1278.58 233.15,1517.38 122.62,1517.38 73.15,1566.85 C101.1@73.15,1870 73.15,1953.15 190,2070 962.99,2070 L103.2@1042.36,1990.63
  Bottom Layer w50: L102.3@233.15,1278.58 233.15,1517.38 122.62,1517.38 73.15,1566.85 C101.1@73.15,1870 73.15,1953.15 190,2070 962.99,2070 L103.2@1042.36,1990.63
NetC102_1: C102.1 C106.1 D102.2 D104.1 D106.2 L103.3 | length 3025.3
  Top Layer w50: C106.1@863.94,990 825.02,1028.92 C102.1@825.02,1367.33 825.02,1407.15 987.24,1569.37 L103.3@1042.36,1569.37
  Signal Layer 2 w50: C106.1@863.94,990 825.02,1028.92 C102.1@825.02,1367.33 825.02,1415.02 979.37,1569.37 L103.3@1042.36,1569.37
  Bottom Layer w20: D104.1@1109.64,397.51 1120,387.15 D106.2@1120,228.74
  Bottom Layer w50: L103.3@1042.36,1569.37 987.24,1569.37 825.02,1407.15 C102.1@825.02,1367.33 825.02,1028.92 C106.1@863.94,990 863.94,903.21 D102.2@1109.64,657.51 D104.1@1109.64,397.51
NetC103_2: C103.2 Q100.4 RT100.2 | length 625.4
  Bottom Layer w50: Q100.4@2548.43,714.57 RT100.2@2548.43,890 2639.23,980.81 C103.2@2960.81,980.81
NetC104_2: C104.2 C110.2 F100.2 L102.1 RV100.1 | length 2975.5
  Top Layer w50: L102.1@626.85,1101.42 626.85,857.64 C104.2@626.98,857.51 640,844.49 RV100.1@640,544.2 640,506.85 C110.2@746.85,400 816.85,330 F100.2@870,330
  Signal Layer 1 w50: L102.1@626.85,1101.42 626.85,857.64 C104.2@626.98,857.51 ; RV100.1@640,544.2 640,506.85 C110.2@746.85,400 816.85,330 F100.2@870,330
  Signal Layer 2 w50: L102.1@626.85,1101.42 626.85,857.64 C104.2@626.98,857.51 ; RV100.1@640,544.2 640,506.85 C110.2@746.85,400 816.85,330 F100.2@870,330
  Bottom Layer w50: C104.2@626.85,857.64 L102.1@626.85,1101.42 ; C104.2@626.98,857.51 640,844.49 RV100.1@640,544.2 640,506.85 C110.2@746.85,400 816.85,330 F100.2@870,330
NetC105_2: C105.2 C111.2 L102.2 L103.1 | length 5274.7
  Top Layer w50: L102.2@626.85,1278.58 626.85,1517.38 C105.2@626.98,1517.51 716.85,1607.38 C111.2@716.85,1750 746.85,1780 1280,1780 1337.64,1837.64 L103.1@1337.64,1990.63
  Signal Layer 1 w50: L102.2@626.85,1278.58 626.98,1278.71 C105.2@626.98,1517.51 716.85,1607.38 C111.2@716.85,1750 746.85,1780 1280,1780 1337.64,1837.64 L103.1@1337.64,1990.63
  Signal Layer 2 w50: L102.2@626.98,1278.71 C105.2@626.98,1517.51 716.85,1607.38 C111.2@716.85,1750 746.85,1780 1280,1780 1337.64,1837.64 L103.1@1337.64,1990.63
  Bottom Layer w50: L102.2@626.98,1278.71 C105.2@626.98,1517.51 716.85,1607.38 C111.2@716.85,1750 746.85,1780 1280,1780 1337.64,1837.64 L103.1@1337.64,1990.63
NetC106_2: C106.2 C112.2 D101.2 D103.1 D107.2 L103.4 | length 2996.5
  Top Layer w20: D107.2@1120,228.74 D103.1@1120,387.15
  Top Layer w50: D103.1@1109.64,397.51 D101.2@1109.63,657.51 1109.63,849.63 1250,990 C106.2@1356.06,990 1356.06,1071.75 1484.98,1200.67 C112.2@1484.98,1242.67 1484.98,1325.02 1337.64,1472.36 L103.4@1337.64,1569.37
  Signal Layer 2 w50: L103.4@1337.64,1569.37 1337.64,1472.36 1484.98,1325.02 C112.2@1484.98,1242.67 1484.98,1200.67 1356.06,1071.75 C106.2@1356.06,990
  Bottom Layer w50: L103.4@1337.64,1569.37 1337.64,1472.36 1484.98,1325.02 C112.2@1484.98,1242.67 1484.98,1200.67 1356.06,1071.75 C106.2@1356.06,990
NetC107_2: C107.2 D101.1 D102.1 L101.1 | length 911
  Bottom Layer w50: D102.1@1390.62,657.51 1684.69,657.51 L101.1@1890,452.2 2062.2,280 C107.2@2145.28,280
  other v1: 1480,600 1510,600 1480,640 1510,640 1480,680 1510,680 1480,720 1510,720
NetC108_2: C108.2 L100.11 L101.2 | length 1456.7
  Top Layer w50: L100.11@1960.13,1947.51 1960.13,1075.15 C108.2@2145.28,890
  Bottom Layer w50: L101.2@1890,727.8 2052.2,890 C108.2@2145.28,890
NetC109_1: C109.1 C114.1 C115.1 R105.1 R108.2 R110.1 | length 472.9
  Bottom Layer w20: C109.1@2570,1940 2570,2022.91 R105.1@2587.09,2040 2637.09,2090 2700,2090 2732.99,2057.01 R108.2@2732.99,2050 C115.1@2732.99,1930 ; R108.2@2740,2050 R110.1@2798.5,2050
NetC109_2: C109.2 D100.1 D100.3 L100.2 Q101.4 R100.2 | length 1543.3
  Bottom Layer w20: Q101.4@2040,1675.51 2072.91,1708.43 2072.91,1940 ; R100.2@2072.91,2040 2072.91,1940 ; C109.2@2490,1940 2072.91,1940
  Bottom Layer w50: L100.2@1760.13,1747.51 Q101.4@1968,1747.51 ; Q101.4@2040,1675.51 2195.75,1519.76 D100.3@2336.14,1519.76 D100.1@2336.14,1340.24
NetC113_1: C113.1 Q100.1 Q102.3 R103.2 | length 275.4
  Top Layer w20: Q102.3@2301.65,637.24 2318.9,620 v1(2350.94,620)
  Bottom Layer w20: C113.1@2181.5,610 Q100.1@2265.91,610 ; C113.1@2190,618.5 R103.2@2190,678.5 ; Q100.1@2276.38,620 v1(2350.94,620)
NetC114_2: C114.2 C115.2 Q101.3 R104.1 R108.1 R112.2 R113.2 R114.2 | length 2403.9
  Signal Layer 1 w20: v1(1820,1120) 1850.58,1120 1940.58,1210 2320.71,1210 2430.6,1100.11 2480.11,1100.11 2850,1470 2850,1700 v1(2620,1930)
  Bottom Layer w20: v1(1820,1120) R113.2@1820,1153.35 ; 1963.35,1150 R104.1@2020,1150 ; v1(2620,1930) 2670,1930 R108.1@2670,2050
  Bottom Layer w50: R112.2@1724.45,1157.8 R113.2@1824.45,1157.8 R114.2@1924.45,1157.8 1940,1173.35 Q101.3@1940,1273.94
NetC116_2: C116.2 Q102.1 Q103.3 R111.1 | length 212.8
  Top Layer w20: Q103.3@2262.76,320 R111.1@2262.76,414.25 ; R111.1@2264.25,424.25 Q102.1@2264.25,542.76
NetC117_2: C117.2 D108.1 R116.2 | length 151.4
  Top Layer w20: R116.2@2484.78,356.28 D108.1@2484.78,420 2490,420 2520,450 C117.2@2520,490
NetC118_1: C118.1 C120.1 U100.6 | length 98.1
  Bottom Layer w20: U100.6@2964.13,1752.6 3014.09,1752.6 C118.1@3014.09,1704.41
NetC118_2: C118.2 R122.2 | length 57
  Bottom Layer w20: C118.2@3081.5,1700 R122.2@3081.5,1757.01
NetC119_1: C119.1 D109.1 R121.2 | length 451.9
  Top Layer w25: R121.2@2860,2040 C119.1@3029.37,2040 ; D109.1@3030,1844.47 3100,1914.47 3100,2020 3080.63,2039.37 C119.1@3030,2039.37
NetC121_1: C121.1 R121.1 U100.3 | length 244.4
  Top Layer w20: v1(2831.57,1880) 2860,1908.43 R121.1@2860,1960
  Bottom Layer w20: C121.1@2831.57,1970 2831.57,1851.69 U100.3@2855.87,1827.4
NetC122_1: C122.1 R110.2 U100.2 | length 301.3
  Bottom Layer w12: U100.2@2855.87,1790 2870,1790 2898.5,1818.5 C122.1@2898.5,1890 2898.5,2012.99 R110.2@2861.5,2050
NetC123_1: C123.1 R117.1 R118.1 R123.2 R124.2 U100.1 | length 308.9
  Bottom Layer w12: R118.1@2792.64,1752.6 U100.1@2855.87,1752.6 2848.5,1745.24 R124.2@2848.5,1630 R123.2@2848.5,1570
  Bottom Layer w20: R117.1@2791.5,1691.46 R118.1@2791.5,1751.46
NetC201_2: C201.2 C205.1 C206.2 C207.1 T200.2 | length 4447.7
  Top Layer w12: v1(2940,170) 2940,540 3120,720 3120,1310 3350,1540 3350,2040.27 ; C201.2@3427.37,2026.25 C201.2@3441.39,2040.27
  Top Layer w100: C205.1@3236.03,2040.27 3350,2040.27 3413.35,2040.27 3427.37,2026.25 T200.2@3718.82,1734.8
  Signal Layer 1 w100: C205.1@3236.03,2040.27 3413.35,2040.27 T200.2@3718.82,1734.8
  Signal Layer 2 w100: C205.1@3236.03,2040.27 3413.35,2040.27 T200.2@3718.82,1734.8
  Bottom Layer w12: v1(2940,170) 3057.09,52.91 C207.1@3140,52.91 C206.2@3240,52.91
  Bottom Layer w100: C205.1@3236.03,2040.27 C201.2@3441.39,2040.27 C201.2@3447.37,2040.27
NetC204_1: C204.1 R202.1 U200.4 | length 154.2
  Bottom Layer w25: C204.1@4607.09,1660 4604.29,1657.2 U200.4@4604.29,1585.59 4672.91,1585.59 R202.1@4680,1578.5
NetC216_1: C216.1 U201.3 | length 179.6
  Bottom Layer w10: U201.3@4780,1950 4810,1980 4888.5,1980 C216.1@4930,2021.5
NetC218_1: C218.1 U202.3 | length 184.4
  Bottom Layer w10: U202.3@4597.4,1244.13 4597.4,1247.4 4630,1280 4694.9,1280 4740,1325.1 C218.1@4740,1331.5
NetC220_1: C220.1 D204.1 U203.14 | length 256.6
  Bottom Layer w20: U203.14@3425,486.3 3425,664.68 D204.1@3480.31,720
NetC221_1: C221.1 R213.2 R216.2 R221.2 R222.2 | length 430.6
  Top Layer w20: R216.2@4381.5,51.1 R221.2@4381.5,120 4381.5,192.6 4408.9,220 4478.54,220 4511.5,187.05 C221.1@4511.5,180 R222.2@4511.5,120 R213.2@4578.5,120
NetC221_2: C221.2 R222.1 R224.2 R230.2 U205.1 | length 216.3
  Top Layer w20: R230.2@4448.5,53.5 R222.1@4448.5,120 C221.2@4448.5,180
  Bottom Layer w20: R224.2@4381.5,51.1 U205.1@4441.26,51.1 ; U205.1@4442.76,52.6 U205.1@4447.6,52.6 ; U205.1@4450,59.84 v1(4450,85)
NetC222_1: C222.1 R224.1 | length 68.9
  Bottom Layer w20: R224.1@4318.5,51.1 C222.1@4318.5,120
NetC222_2: C222.2 R221.1 U204.2 U205.2 | length 265
  Top Layer w20: U204.2@4250,160 4278.5,160 R221.1@4318.5,120 4340,141.5 v1(4340,170)
  Bottom Layer w20: v1(4340,170) 4381.5,128.5 C222.2@4381.5,120 ; C222.2@4388.9,127.4 U205.2@4442.76,127.4
NetC232_1: C232.1 R225.1 R227.2 U203.9 | length 225.1
  Top Layer w20: v1(3120,540) 3158.5,540 R225.1@3178.5,560
  Bottom Layer w20: R227.2@3050,491.5 C232.1@3110,491.5 U203.9@3169.8,491.5 ; C232.1@3120,501.5 v1(3120,540)
NetC300_1: C300.1 R302.2 U300.4 U300.6 | length 198.1
  Bottom Layer w12: C300.1@4666.28,947.56 U300.4@4720.02,947.56 4720.02,930.07 4733.14,916.95 4758.08,916.95 4771.2,930.07 U300.6@4771.2,947.56 R302.2@4771.2,994.86
NetC302_1: C302.1 R308.1 U302.3 | length 129.8
  Top Layer w10: U302.3@4827.4,429.02 4846.42,410 R308.1@4890,410
  Top Layer w12: R308.1@4896.38,410 C302.1@4896.38,469.29
NetC302_2: C302.2 R307.1 U302.4 | length 183.9
  Top Layer w12: U302.4@4827.4,537.28 4860.12,570 4882.91,570 C302.2@4910,597.09 ; C302.2@4913.46,593.62 R307.1@4990,593.62
NetC303_1: C303.1 R306.1 R312.2 U301.3 | length 170.9
  Bottom Layer w20: U301.3@4584.13,252.6 4620.35,216.38 4690,216.38 R306.1@4740,216.38
NetC304_1: C304.1 R310.2 U301.1 | length 190.4
  Bottom Layer w20: U301.1@4584.13,327.4 4598.19,327.4 4634.41,363.62 C304.1@4640,363.62 4653.62,350 4670,350 4703.62,316.38 R310.2@4740,316.38
NetC306_1: C306.1 D302.1 Q301.1 R313.2 R314.2 | length 223.5
  Bottom Layer w20: Q301.1@3451.65,131.69 D302.1@3451.65,180 ; Q301.1@3455.94,127.4 R314.2@3518.5,127.4 ; R314.2@3518.5,121.69 R314.2@3518.5,127.4 ; R313.2@3518.5,180 R314.2@3518.5,127.4 ; C306.1@3572.8,127.4 R314.2@3518.5,127.4
NetC307_1: C307.1 Q302.1 R315.1 R316.1 R317.2 | length 605.2
  Top Layer w20: C307.1@3530,78.5 3636.85,78.5 Q302.1@3652.6,62.76 3679.84,90 v1(3680,90) ; v1(3770,360) R315.1@3817.05,360 ; R315.1@3818.5,358.54 R316.1@3818.5,418.54
  Signal Layer 1 w20: v1(3680,90) 3680,189.48 3797.87,307.35 3797.87,332.13 v1(3770,360)
NetD105_1: D105.1 R107.2 | length 75.2
  Bottom Layer w20: D105.1@2113.31,1060 R107.2@2188.5,1060
NetD105_2: D105.2 Q101.1 R102.2 R104.2 | length 324.5
  Bottom Layer w20: D105.2@2026.69,1060 2050,1060 2080,1090 2080,1130 R104.2@2100,1150 R102.2@2171.04,1150 ; 2140,1154.48 Q101.1@2140,1273.94
NetD200_2: D200.2 Q200.1 R200.2 R201.2 | length 189.4
  Bottom Layer w20: D200.2@4090,1513.31 R200.2@4090,1570 ; R200.2@4091.5,1591.5 R201.2@4139.76,1591.5 ; R201.2@4139.76,1601.73 Q200.1@4139.76,1686.14
NetD201_2: D201.2 Q202.1 R205.2 R208.2 | length 281.9
  Bottom Layer w20: D201.2@3880,963.31 3938.19,963.31 R208.2@3950,951.5 3950,1020 R205.2@3960,1030 3980,1050 3980,1103.76 Q202.1@4009.89,1133.65
NetD202_1: D202.1 R231.2 | length 120.1
  Bottom Layer w25: R231.2@2760,697.09 D202.1@2880.08,697.09
NetD202_2: D202.2 R210.2 T200.5 | length 2286
  Top Layer w25: v1(3050,160) R210.2@3097.2,160
  Signal Layer 1 w12: v1(3050,160) 3400,160 3410,170 3410,337.79 3392.7,355.09 3392.7,759.08 T200.5@3718.82,1085.2
  Bottom Layer w25: D202.2@3067.01,710 3067.01,727.1 3279.36,939.45 3573.07,939.45 T200.5@3718.82,1085.2
NetD204_2: D204.2 R212.2 | length 88.5
  Bottom Layer w12: R212.2@3320,631.5 R212.2@3320,631.81
  Bottom Layer w20: R212.2@3319.68,631.81 D204.2@3319.68,720
NetD206_1: D206.1 R215.1 | length 93.7
  Bottom Layer w20: D206.1@3734.92,284.47 3755.63,263.76 R215.1@3820,263.76
NetD300_1: D300.1 D301.1 U300.3 | length 696
  Bottom Layer w12: D301.1@4408.54,327.4 4408.54,599.04 4642.81,833.31 D300.1@4650,833.31 4703.31,833.31 4720.02,850.02 U300.3@4720.02,858.97
NetD300_2: D300.2 R300.1 | length 70.7
  Bottom Layer w12: D300.2@4653.43,743.27 R300.1@4724.11,743.27
NetD301_2: D301.2 U301.4 | length 67.3
  Bottom Layer w20: D301.2@4408.54,252.6 U301.4@4475.87,252.6
NetD301_3: D301.3 R305.1 U303.2 | length 209.4
  Top Layer w20: U303.2@4250,370 4261.5,370 R305.1@4310,321.5
  Bottom Layer w20: U303.2@4250,370 4288.9,370 4310,348.9 4310,294.06 D301.3@4314.06,290
NetF100_1: F100.1 TP_L.1 | length 882.5
  Top Layer w50: TP_L.1@650.13,117.51 857.51,117.51 F100.1@870,130
  Signal Layer 1 w50: TP_L.1@650.13,117.51 857.51,117.51 F100.1@870,130
  Signal Layer 2 w50: TP_L.1@650.13,117.51 857.51,117.51 F100.1@870,130
  Bottom Layer w50: TP_L.1@650.13,117.51 F100.1@857.51,117.51
NetQ103_1: Q103.1 R116.1 R119.2 R120.2 | length 176.9
  Top Layer w20: Q103.1@2357.24,282.6 R119.2@2414.09,282.6 ; R119.2@2420,288.5 R120.2@2540,288.5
